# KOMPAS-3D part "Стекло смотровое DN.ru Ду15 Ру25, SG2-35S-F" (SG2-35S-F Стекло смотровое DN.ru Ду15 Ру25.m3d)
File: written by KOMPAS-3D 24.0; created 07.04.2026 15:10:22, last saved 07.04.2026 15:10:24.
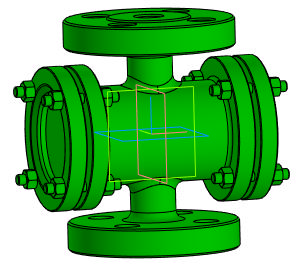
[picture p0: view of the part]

Document properties: Автор: Main; Полное имя файла: D:\DN.ru Аутсерс\Стекло смотровое DN.ru\SG2-35S-F Стекло смотровое DN.ru Ду15 Ру25\SG2-35S-F Стекло смотровое DN.ru Ду15 Ру25.m3d

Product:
- Body: Тело 1  | qty 1
    Масса: 3.175709
- Part/product: Стекло смотровое DN.ru Ду15 Ру25  | designation SG2-35S-F
    Масса: 4
    Раздел спецификации: Прочие изделия
    Примечание: D500-00091

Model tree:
1. Операция без истории:1

Expressions: SG2-35S-F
